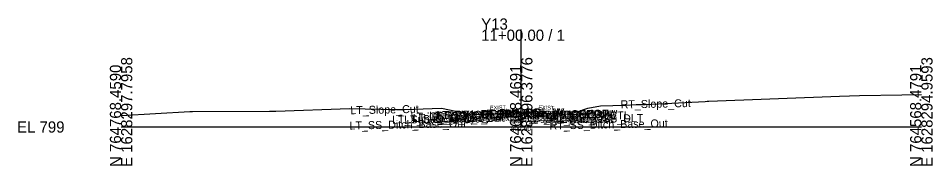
# Model space of a CAD drawing. Extents: x -26 to 203, y -10 to 3517.
# Drawn here: x -25.7 to 202.8, y 1990.3 to 2027.2 of the extents above; entities that cross this region are included whole.
import ezdxf

# ---------------------------------------------------------------- set-up
doc = ezdxf.new("R2010")
doc.units = 0
for name, color, linetype in [('Default', 7, 'Continuous'), ('Exist Cross Section Cell', 7, 'Continuous'), ('Exist XS Center Line Elevation Label', 7, 'Continuous'), ('Exist XS Ground Line', 7, 'Continuous'), ('Prop XS SE Text', 7, 'Continuous'), ('Scratch_Level_0', 7, 'Continuous')]:
    doc.layers.add(name, color=color, linetype=linetype)

msp = doc.modelspace()

# ---------------------------------------------------------------- linework, layer by layer
at = {"layer": 'Exist Cross Section Cell'}
for p, q in [((100, 2000), (100, 2024.36)), ((0, 2000), (100, 2000)), ((100, 2000), (200, 2000))]:
    msp.add_line(p, q, dxfattribs=at)
at = {"layer": 'Exist XS Ground Line'}
msp.add_lwpolyline([(0, 2002.84), (17.16, 2003.9), (17.85, 2003.91), (37.13, 2003.95), (38.69, 2003.97), (57.08, 2004.63), (68.86, 2004.37), (70.91, 2004.36), (73.16, 2004.5), (80.09, 2004.7), (85.63, 2003.52), (88.3, 2003.11), (96.52, 2003.46), (100.21, 2003.6), (109.18, 2003.29), (112.11, 2003.17), (112.36, 2003.46), (113.96, 2003.83), (116.62, 2004.67), (119.82, 2005.29), (125.96, 2005.49), (128.73, 2005.63), (130.99, 2005.63), (145.97, 2006.4), (146.45, 2006.46), (146.91, 2006.47), (179.54, 2007.75), (184.51, 2007.89), (195.1, 2008.06), (200, 2008.12)], dxfattribs=at)

# ---------------------------------------------------------------- texts
at = {"layer": 'Default'}
msp.add_text('-', height=0.0001, dxfattribs=at).set_placement((0, 2000))
at = {"layer": 'Exist Cross Section Cell'}
for s, p in [('Y13', (90, 2024.36)), ('11+00.00 / 1', (90, 2021.56)), ('EL 799', (-26, 1998.6))]:
    msp.add_text(s, height=2.8, dxfattribs=at).set_placement(p)
for s, p in [('E 1628297.7958', (2.8, 1990)), ('E 1628296.3776', (102.8, 1990)), ('E 1628294.9593', (202.8, 1990)), ('N 764768.4590', (0, 1990)), ('N 764668.4691', (100, 1990)), ('N 764568.4791', (200, 1990))]:
    msp.add_text(s, height=2.8, rotation=90, dxfattribs=at).set_placement(p)
at = {"layer": 'Exist XS Center Line Elevation Label'}
msp.add_text('802.60', height=1.2, dxfattribs=at).set_placement((97.39, 1999))
at = {"layer": 'Prop XS SE Text'}
for rotation, p in [(2.2906, (92.19, 2004.29)), (357.7094, (104.27, 2004.43))]:
    msp.add_text('EXIST.', height=1, rotation=rotation, dxfattribs=at).set_placement(p)
at = {"layer": 'Scratch_Level_0'}
for s, p in [('RT_Slope_Cut', (124.86, 2004.64)), ('LT_Slope_Cut', (57.31, 2003.19)), ('LT_PV1_OEEOP_W', (77.01, 2001.8)), ('LT_PV1_OEOT', (78.76, 2001.94)), ('LT_PS1_OEOP', (78.82, 2001.94)), ('LT_PV1_OEEOP', (78.9, 2001.96)), ('RT_PV1_PGL_W', (89.86, 2002.27)), ('LT_PV1_PGL_W', (89.91, 2002.27)), ('PV2_PGL', (93.93, 2002.23)), ('PV1_PGL', (94.49, 2002.49)), ('RT_PV1_OEEOP_W', (98.95, 2001.79)), ('RT_PV1_OEEOP', (100.84, 2001.96)), ('RT_PV1_OEOT', (102.71, 2001.93)), ('RT_PS1_OEOP', (102.78, 2001.94)), ('LT_Sub_OSS_DLT', (67.74, 2000.8)), ('LT_Sub_Trench_Out', (70.79, 2000.86)), ('LT_GS_OS_CTL', (72.39, 2001.51)), ('LT_PS3_Shelf_Out', (72.91, 2001.23)), ('LT_PV2_OEEOP_W', (76.44, 2001.66)), ('LT_PV3_OEEOP_W', (76.44, 2001.33)), ('LT_PS3_OEOP', (77.66, 2001.33)), ('LT_PS2_OEOP', (78, 2001.67)), ('LT_Sub_OEOT', (78.1, 2001.01)), ('LT_PV2_OEOT', (78.2, 2001.67)), ('LT_PV3_OEOT', (78.2, 2001.34)), ('Sub_PGL', (93.83, 2001.56)), ('PV3_PGL', (93.93, 2001.89)), ('RT_Sub_Trench_Out', (97.62, 2000.86)), ('RT_PV2_OEEOP_W', (98.39, 2001.66)), ('RT_PV3_OEEOP_W', (98.39, 2001.32)), ('RT_PS3_Shelf_Out', (99.06, 2001.23)), ('RT_Sub_OEOT', (102.05, 2001)), ('RT_PV2_OEOT', (102.15, 2001.67)), ('RT_PV3_OEOT', (102.15, 2001.34)), ('RT_PS2_OEOP', (102.47, 2001.67)), ('RT_PS3_OEOP', (102.81, 2001.33)), ('RT_GS_OS_CTL', (106.34, 2001.51)), ('RT_Sub_OSS_DLT', (107.06, 2000.8)), ('LT_SS_Ditch_Base_Out', (57.1, 1999.36)), ('RT_SS_Ditch_Base_Out', (107.06, 1999.36))]:
    msp.add_text(s, height=2, rotation=1.1458, dxfattribs=at).set_placement(p)

doc.saveas('drawing.dxf')
